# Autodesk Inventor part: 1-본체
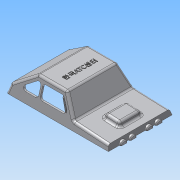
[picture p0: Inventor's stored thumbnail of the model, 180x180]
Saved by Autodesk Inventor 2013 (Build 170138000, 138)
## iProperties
Created: 2015-05
Part Number: 1-본체
Material: ABS 플라스틱
Document SubType Name: Modeling
Designer: ST
Density: 1.06 g/cm^3
Mass: 30.4732 g
Surface Area: 305.118 cm^2
Volume: 28.7483 cm^3
Author: ST
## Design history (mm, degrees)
sketch "스케치1"
  geometry: L1 (-61, 38)-(61, 38); L2 (61, 38)-(61, -38); L3 (61, -38)-(-61, -38); L4 (-61, -38)-(-61, 38); 4 further points
  constraints: 8 end point, 2 midpoint, 2 parallel, 1 coincident, 1 horizontal, 1 horizontal alignment, 1 perpendicular, 1 vertical alignment
  dimensions: "d0" = 122 distance of L1.start L1.end; "d2" = 76 distance of L1.end L2.end
extrude "돌출1" new body sketch "스케치1" distance "d3" = 30; taper "d4" = -15 deg
sketch "스케치2"
  geometry: L1 (-52.962, 30)-(52.962, 30) reference; L2 (31, 30)-(58.321, 10); L3 (61, 0)-(52.962, 30) reference; 1 further point
  constraints: 2 end point, 2 point on line
  dimensions: "d5" = 30 horizontal distance of L3.start L2.start; "d7" = 20 distance from line of L1 L2.end
extrude "돌출2" cut sketch "스케치2" stored distance "d8" = 31; taper "d9" = 0 deg
sketch "스케치3"
  geometry: L1 (-61, 0)-(-52.962, 30) reference; L2 (-59.392, 6)-(-17.392, 8.201); L3 (-61, 0)-(61, 0) reference; L4 (-52.962, 30)-(31, 30) reference; L5 (-17.392, 8.201)-(-3.771, 30); 1 further point
  constraints: 4 end point, 2 point on line
  dimensions: "d10" = 3 deg angle of L3 L2; "d11" = 6 vertical distance of L2.start L1.start; "d13" = 42 horizontal distance of L2.end L2.start; "d14" = 125 deg angle of L5 L2
extrude "돌출3" cut sketch "스케치3" stored distance "d15" = 0; taper "d16" = 0 deg
feature "쉘1" dims "d17" = 2
sketch "스케치4"
  geometry: L1 (61, 38)-(-61, 38) reference; L2 (-61, 38)-(-61, -38) reference; L3 (61, -38)-(61, 38) reference; L4 (-61, -38)-(61, -38) reference; L5 (-60, 37)-(60, 37); L6 (60, 37)-(60, -37); L7 (60, -37)-(-60, -37); L8 (-60, -37)-(-60, 37); L9 (-58.929, -35.929)-(-58.929, 35.929) reference; L10 (-58.929, 35.929)-(58.929, 35.929) reference; L11 (58.929, -35.929)-(-58.929, -35.929) reference; L12 (58.929, 35.929)-(58.929, -35.929) reference; 1 further point
  constraints: 8 end point, 3 other
  dimensions: "d18" = 1 distance between parallel lines of L1 L5
extrude "돌출4" join sketch "스케치4" distance "d19" = 1; taper "d20" = 0 deg
sketch "스케치5" dims "d127" = 3
  geometry: L1 (-59.392, 6)-(-17.392, 8.201) reference; L2 (-50, 6.492)-(-48.444, 11.581); L3 (-48.444, 11.581)-(-32.106, 12.437); L4 (-32.106, 12.437)-(-30.027, 7.539); L5 (-61, 0)-(-59.392, 6) reference; 1 further point
  constraints: 6 end point, 2 point on line, 1 parallel
  dimensions: "d25" = 70 deg angle of L2 L1; "d26" = 70 deg angle of L4 L1; "d27" = 5 distance between parallel lines of L3 L1; "d29" = 20 distance of L4.end L2.start; "d31" = 11 horizontal distance of L2.start L5.start
extrude "돌출5" join sketch "스케치5" stored distance "d32" = 26; taper "d33" = 0 deg
sketch "스케치6"
  geometry: L1 (-61, 38)-(-61, -38) reference; C1 r 3 at (-40, 0); C2 r 3 at (0, -22); C3 r 3 at (40, 0); C4 r 3 at (0, 22); 2 further points
  constraints: 4 centre point, 3 equal radius, 2 horizontal alignment, 2 vertical alignment, 1 midpoint
  dimensions: "d34" = 6 diameter of C1; "d36" = 40 distance of point (0, 0) C1.centre; "d37" = 40 distance of C3.centre point (0, 0); "d38" = 22 distance of C4.centre point (0, 0); "d39" = 44 distance of C2.centre C4.centre
extrude "돌출6" join sketch "스케치6" stored distance "d40" = 26; taper "d41" = 2 deg
sketch "스케치7"
  geometry: L1 (-57.837, 4.079)-(-16.248, 6.258) reference; L2 (-48.444, 11.581)-(-32.106, 12.437) reference; L3 (-50, 6.492)-(-30.027, 7.539) reference; L4 (-50, 6.492)-(-48.444, 11.581) reference; L5 (-48.444, 11.581)-(-32.106, 12.437) reference; L6 (-32.106, 12.437)-(-30.027, 7.539) reference; L7 (-48.497, 4.568)-(-46.941, 9.657); L8 (-46.941, 9.657)-(-33.4, 10.366); L9 (-33.4, 10.366)-(-31.321, 5.468); 1 further point
  constraints: 6 end point, 2 point on line, 2 other
  dimensions: "d42" = 2 distance between parallel lines of L2 L8
extrude "돌출7" cut sketch "스케치7" stored distance "d43" = 22; taper "d44" = 0 deg
sketch "스케치10"
  geometry: C1 r 3 at (0, 0) reference; 1 further point
extrude "돌출9" join sketch "스케치10" stored distance "d47" = 22; taper "d48" = 2 deg
sketch "스케치12"
  geometry: L1 (-46.327, 9.524)-(-45, 2); L2 (-45, 2)-(-35, 2); L3 (-35, 2)-(-33.526, 10.36); L4 (-46.941, 9.657)-(-33.4, 10.366) reference; L5 (-37, 0)-(-43, 0) reference; L6 (-40, 0)-(-40, 10.02); L7 (-43, 0)-(-43.344, 9.845) reference; L8 (-37, 0)-(-36.644, 10.196) reference; L9 (30.346, 28)-(56.571, 8.802) reference; L10 (35, 2)-(45, 2); L11 (45, 2)-(47.385, 15.527); L12 (43, 0)-(37, 0) reference; L13 (40, 0)-(40, 20.933); L14 (35, 2)-(30.426, 27.942); 3 further points
  constraints: 16 end point, 7 point on line, 4 midpoint, 3 perpendicular, 1 horizontal
  dimensions: "d55" = 2 distance between parallel lines of L2 L5; "d57" = 10 distance of L1.end L2.end; "d58" = 20 deg angle of L3 L1; "d59" = 10 deg angle of L6 L1; "d61" = 10 deg angle of L13 L11; "d62" = 10 deg angle of L14 L13; "d63" = 10 distance of L10.start L10.end; "d64" = 2 distance between parallel lines of L10 L12
extrude "돌출10" join sketch "스케치12" stored distance "d65" = 2; taper "d66" = 0 deg
sketch "스케치13"
  geometry: L1 (-43, 0)-(-43.344, 9.845) reference; L2 (-37, 0)-(-36.644, 10.196) reference; L3 (-37, 0)-(-43, 0) reference; L4 (-46.941, 9.657)-(-33.4, 10.366) reference; L5 (-46.355, 9.687)-(-45, 2); L6 (-45, 2)-(-35, 2); L7 (-35, 2)-(-33.4, 10.366); L8 (-40, 0)-(-40, 10.02); L9 (-60, -1)-(60, -1) reference; 2 further points
  constraints: 8 end point, 3 point on line, 2 midpoint, 1 perpendicular
  dimensions: "d67" = 10 distance of L5.end L6.end; "d71" = 10 deg angle of L8 L5; "d73" = 2 distance between parallel lines of L6 L3
extrude "돌출11" join sketch "스케치13" stored distance "d74" = 2; taper "d75" = 0 deg
sketch "스케치14"
  geometry: L1 (-28.427, 28)-(-33.571, 8.802) reference; L2 (-30.331, 20.893)-(-27, 2); L3 (-27, 2)-(-17, 2); L4 (-17, 2)-(-12.415, 28); L5 (12.415, 28)-(17, 2); L6 (17, 2)-(27, 2); L7 (29.962, 30)-(-29.962, 30) reference; L8 (27, 2)-(30.331, 20.893); L9 (-19, 0)-(-25, 0) reference; L10 (25, 0)-(19, 0) reference; L11 (-22, 0)-(-22, 28); L12 (25.978, 28)-(18.022, 28) reference; L13 (22, 28)-(22, 0); L14 (33.571, 8.802)-(28.427, 28) reference; 5 further points; 1 other entity
  constraints: 16 end point, 5 midpoint, 4 point on line, 3 parallel, 1 horizontal, 1 perpendicular, 4 other
  dimensions: "d76" = 20 deg angle of L4 L2; "d77" = 10 distance of L2.end L3.end; "d79" = 10 distance of L5.end L6.end; "d80" = 2 distance between parallel lines of L3 L9; "d81" = 2 distance between parallel lines of L6 L10; "d82" = 10 deg angle of L11 L4
extrude "돌출12" join sketch "스케치14" stored distance "d83" = 2; taper "d84" = 0 deg
sketch "스케치15"
  geometry: C1 r 3 at (-40, 22) reference; C2 r 3 at (0, 44) reference; C3 r 3 at (0, 0) reference; C4 r 3 at (40, 22) reference; 5 further points
  constraints: 4 coincident
hole "구멍1" sketch "스케치15" at (-40, 22), (0, 44), (0, 0), (40, 22) diameter "d85" = 3.242; stored, may be unused: countersink angle "d89" = 90 deg, drill point angle "d91" = 118 deg; dims "d86" = 9, "d87" = 4, "d88" = 2, "d90" = 11
node "작업 평면1"
sketch "스케치16"
  geometry: L1 (3.771, 30)-(-31, 30) reference; L2 (17.392, 8.201)-(3.771, 30) reference; L3 (-31, 30)-(-58.321, 10) reference; L4 (0.999, 25)-(10.372, 10); L5 (10.372, 10)-(-23.628, 10); L6 (58.929, -1)-(-58.929, -1) reference; L7 (-23.628, 10)-(-23.628, 25); L8 (-25.628, 25)-(-25.628, 10); L9 (-25.628, 10)-(-53.628, 10); L10 (-49.856, 10)-(-29.365, 25); L11 (-29.365, 25)-(-25.628, 25); L12 (-23.628, 25)-(0.999, 25); L13 (-25.628, 10)-(-49.856, 10); 1 further point
  constraints: 18 end point, 5 perpendicular, 2 parallel, 1 horizontal alignment, 1 point on line
  dimensions: "d94" = 5 distance between parallel lines of L2 L4; "d96" = 34 distance of L4.end L5.end; "d97" = 28 distance of L8.end L9.end; "d98" = 5 distance between parallel lines of L3 L10; "d101" = 15 distance of L8.start L8.end; "d102" = 5 distance between parallel lines of L1 L12; "d103" = 15 distance between parallel lines of L12 L5; "d104" = 2 distance between parallel lines of L7 L8
extrude "돌출13" cut sketch "스케치16" stored distance "d105" = 2; taper "d106" = 0 deg
sketch "스케치17"
  geometry: L1 (-61, -38)-(-61, 38) reference; 2 further points
  constraints: 1 horizontal alignment, 1 other
  dimensions: "d107" = 50 distance from line of point (-11, 0) L1
feature "엠보싱1" sketch "스케치17" dims "d108" = 0.5, "d109" = 0
fillet "모깎기1" dims "d110" = 3
fillet "모깎기2" dims "d111" = 3
fillet "모깎기3" dims "d112" = 3
fillet "모깎기4" dims "d113" = 3
node "작업 평면2"
sketch "스케치18"
  geometry: A1 r 4 centre (-21, 0) between (-17, 0) and (-25, 0); A2 r 4 centre (-10, 0) between (-6, 0) and (-14, 0); A3 r 4 centre (10, 0) between (14, 0) and (6, 0); A4 r 4 centre (21, 0) between (25, 0) and (17, 0); 3 further points
  constraints: 8 point on circle, 4 centre point, 3 equal radius, 13 other
  dimensions: "d115" = 8 diameter of A1; "d117" = 10 distance of A2.centre point (0, 0); "d118" = 10 distance of A3.centre point (0, 0); "d119" = 11 distance of A4.centre A3.centre; "d120" = 11 distance of A2.centre A1.centre
extrude "돌출14" join sketch "스케치18" stored distance "d121" = 0; taper "d122" = 0 deg
chamfer "모따기1" distance "d123" = 1; stored, may be unused: second distance "d124" = 2, angle "d125" = 45 deg
fillet "모깎기5" dims "d126" = 3
fillet "모깎기6" dims "d127" = 3
fillet "모깎기7" dims "d128" = 3
fillet "모깎기8" dims "d129" = 3
fillet "모깎기9" dims "d130" = 3
node "솔리드1"
mirror "대칭1"
node "투영된 루프1"
other parameters: "d92" = -38, "d93" = 5, "d95" = 15, "d114" = 63
